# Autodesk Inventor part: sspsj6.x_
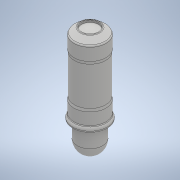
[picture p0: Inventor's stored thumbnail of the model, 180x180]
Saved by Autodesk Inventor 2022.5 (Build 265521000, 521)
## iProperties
Created: 2018-04
Part Number: sspsj6.x_
Material: 一般
Document SubType Name: Modeling
Designer: imaocorp
Density: 1 g/cm^3
Appearance: 既定
Sending System: SOLIDWORKS 2016-2016286
MC: AMD64
MC_MODEL: AMD64 Family 21 Model 2 Stepping 0, AuthenticAMD
OS: Windows_NT
FRU: Parasolid Version 28.0, build 224,  7-29-2016
FORMAT: text
GUISE: transmit
KEY: sspsj6
FILE: sspsj6.x_t
DATE: Wed Apr 25 10:15:45 2018
Author: imaocorp
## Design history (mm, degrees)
feature "Base1"
node "ソリッド1"
